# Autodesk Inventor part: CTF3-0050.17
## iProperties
Shininess: 64.0
Length Units: 11269
Angle Units: 11279
Time Units: 11290
Mass Units: 11283
Length Display Precision: 3
Angle Display Precision: 2
Compacted: True
Part Number: CTF3-0050.17
Document SubType Name: Modeling
Created: 2004-01
Designer: Lollo
Density: 0.0
Volumn: 0.0
Area: 0.0
PropertySet Name: Model Information
Control State: 0
Master: False
Checked Out: False
Author: Lollo
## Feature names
1. Estrusione3 [Extrusion]
2. Estrusione4 [Extrusion]
3. Foro1 [Hole]
4. Serie circolare1 [Circular Pattern]
5. Foro2 [Hole]
6. Serie circolare2 [Circular Pattern]
